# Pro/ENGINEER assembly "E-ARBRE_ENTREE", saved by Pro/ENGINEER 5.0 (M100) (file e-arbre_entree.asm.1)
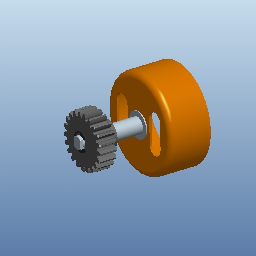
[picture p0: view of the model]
Units: millimeter Newton Second (mmNs); MM, TONNE, HOURS

Other components: 6-CLOCHE_EMBRAYAGE1, PIGNON_Z21-M-1_5, SEGMENT_ARRET_RADIAL_8X0-7

Other named items: A-DROITE, A-DESSUS, A-FACE, A-R0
